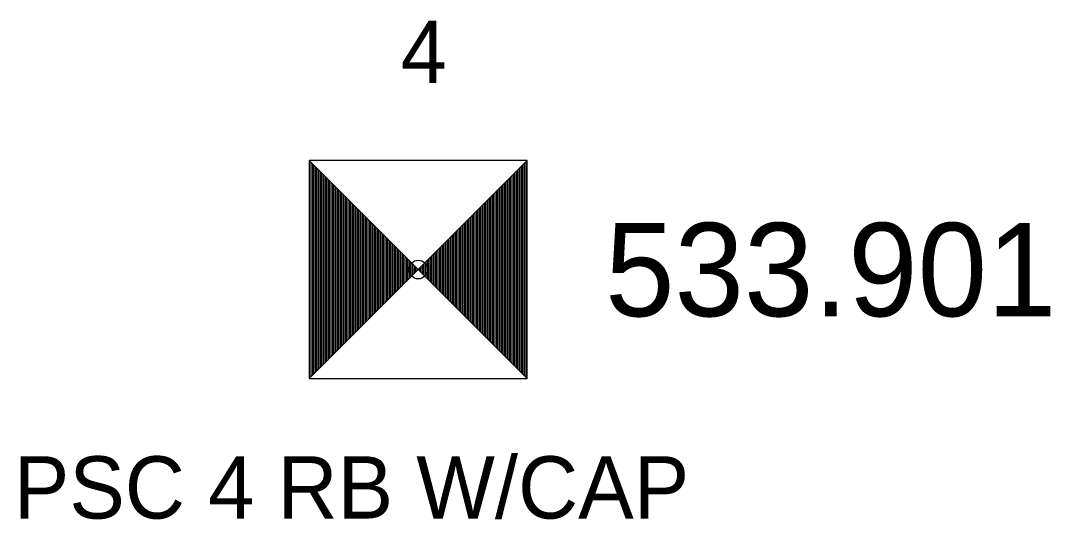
# Model space of a CAD drawing. Extents: x 1649047 to 1650429, y 896228 to 898747.
# Drawn here: x 1649763.56 to 1649780.1, y 898738.7 to 898746.72 of the extents above; entities that cross this region are included whole.
import ezdxf

# ---------------------------------------------------------------- set-up
doc = ezdxf.new("R2010")
doc.units = 0
for name, color, linetype in [('RD_HC_Survey', 7, 'Continuous'), ('RD_HC_Survey_ELEV', 7, 'Continuous'), ('RD_HC_txCode', 7, 'Continuous'), ('RD_SMD_Locator', 7, 'Continuous')]:
    doc.layers.add(name, color=color, linetype=linetype)

msp = doc.modelspace()

# ---------------------------------------------------------------- linework, layer by layer
at = {"layer": 'RD_HC_Survey'}
for p, q in [((1649768.199, 898744.466), (1649771.698, 898740.966)), ((1649771.698, 898744.466), (1649768.199, 898740.966)), ((1649768.223, 898744.441), (1649768.223, 898740.991)), ((1649768.248, 898744.417), (1649768.248, 898741.016)), ((1649768.273, 898744.392), (1649768.273, 898741.04)), ((1649768.298, 898744.367), (1649768.298, 898741.065)), ((1649768.322, 898744.342), (1649768.322, 898741.09)), ((1649771.575, 898744.342), (1649771.575, 898741.09)), ((1649771.599, 898744.367), (1649771.599, 898741.065)), ((1649771.624, 898744.392), (1649771.624, 898741.04)), ((1649771.649, 898744.417), (1649771.649, 898741.016)), ((1649771.674, 898744.441), (1649771.674, 898740.991)), ((1649768.347, 898744.318), (1649768.347, 898741.115)), ((1649768.372, 898744.293), (1649768.372, 898741.139)), ((1649768.396, 898744.268), (1649768.396, 898741.164)), ((1649768.421, 898744.243), (1649768.421, 898741.189)), ((1649768.446, 898744.219), (1649768.446, 898741.214)), ((1649768.471, 898744.194), (1649768.471, 898741.238)), ((1649768.495, 898744.169), (1649768.495, 898741.263)), ((1649771.402, 898744.169), (1649771.402, 898741.263)), ((1649771.426, 898744.194), (1649771.426, 898741.238)), ((1649771.451, 898744.219), (1649771.451, 898741.214)), ((1649771.476, 898744.243), (1649771.476, 898741.189)), ((1649771.501, 898744.268), (1649771.501, 898741.164)), ((1649771.525, 898744.293), (1649771.525, 898741.139)), ((1649771.55, 898744.318), (1649771.55, 898741.115)), ((1649768.52, 898744.144), (1649768.52, 898741.288)), ((1649768.545, 898744.12), (1649768.545, 898741.313)), ((1649768.57, 898744.095), (1649768.57, 898741.337)), ((1649768.594, 898744.07), (1649768.594, 898741.362)), ((1649768.619, 898744.045), (1649768.619, 898741.387)), ((1649768.644, 898744.021), (1649768.644, 898741.412)), ((1649768.669, 898743.996), (1649768.669, 898741.436)), ((1649771.228, 898743.996), (1649771.228, 898741.436)), ((1649771.253, 898744.021), (1649771.253, 898741.412)), ((1649771.278, 898744.045), (1649771.278, 898741.387)), ((1649771.303, 898744.07), (1649771.303, 898741.362)), ((1649771.327, 898744.095), (1649771.327, 898741.337)), ((1649771.352, 898744.12), (1649771.352, 898741.313)), ((1649771.377, 898744.144), (1649771.377, 898741.288)), ((1649768.693, 898743.971), (1649768.693, 898741.461)), ((1649768.718, 898743.946), (1649768.718, 898741.486)), ((1649768.743, 898743.922), (1649768.743, 898741.511)), ((1649768.768, 898743.897), (1649768.768, 898741.535)), ((1649768.792, 898743.872), (1649768.792, 898741.56)), ((1649768.817, 898743.847), (1649768.817, 898741.585)), ((1649771.08, 898743.847), (1649771.08, 898741.585)), ((1649771.105, 898743.872), (1649771.105, 898741.56)), ((1649771.129, 898743.897), (1649771.129, 898741.535)), ((1649771.154, 898743.922), (1649771.154, 898741.511)), ((1649771.179, 898743.946), (1649771.179, 898741.486)), ((1649771.204, 898743.971), (1649771.204, 898741.461)), ((1649768.842, 898743.823), (1649768.842, 898741.61)), ((1649768.867, 898743.798), (1649768.867, 898741.634)), ((1649768.891, 898743.773), (1649768.891, 898741.659)), ((1649768.916, 898743.748), (1649768.916, 898741.684)), ((1649768.941, 898743.724), (1649768.941, 898741.709)), ((1649768.966, 898743.699), (1649768.966, 898741.733)), ((1649768.99, 898743.674), (1649768.99, 898741.758)), ((1649770.907, 898743.674), (1649770.907, 898741.758)), ((1649770.931, 898743.699), (1649770.931, 898741.733)), ((1649770.956, 898743.724), (1649770.956, 898741.709)), ((1649770.981, 898743.748), (1649770.981, 898741.684)), ((1649771.006, 898743.773), (1649771.006, 898741.659)), ((1649771.03, 898743.798), (1649771.03, 898741.634)), ((1649771.055, 898743.823), (1649771.055, 898741.61)), ((1649769.015, 898743.649), (1649769.015, 898741.783)), ((1649769.04, 898743.625), (1649769.04, 898741.808)), ((1649769.065, 898743.6), (1649769.065, 898741.832)), ((1649769.089, 898743.575), (1649769.089, 898741.857)), ((1649769.114, 898743.55), (1649769.114, 898741.882)), ((1649769.139, 898743.526), (1649769.139, 898741.907)), ((1649769.164, 898743.501), (1649769.164, 898741.931)), ((1649770.733, 898743.501), (1649770.733, 898741.931)), ((1649770.758, 898743.526), (1649770.758, 898741.907)), ((1649770.783, 898743.55), (1649770.783, 898741.882)), ((1649770.808, 898743.575), (1649770.808, 898741.857)), ((1649770.832, 898743.6), (1649770.832, 898741.832)), ((1649770.857, 898743.625), (1649770.857, 898741.808)), ((1649770.882, 898743.649), (1649770.882, 898741.783)), ((1649769.188, 898743.476), (1649769.188, 898741.956)), ((1649769.213, 898743.451), (1649769.213, 898741.981)), ((1649769.238, 898743.427), (1649769.238, 898742.006)), ((1649769.263, 898743.402), (1649769.263, 898742.03)), ((1649769.287, 898743.377), (1649769.287, 898742.055)), ((1649769.312, 898743.353), (1649769.312, 898742.08)), ((1649770.585, 898743.353), (1649770.585, 898742.08)), ((1649770.61, 898743.377), (1649770.61, 898742.055)), ((1649770.634, 898743.402), (1649770.634, 898742.03)), ((1649770.659, 898743.427), (1649770.659, 898742.006)), ((1649770.684, 898743.451), (1649770.684, 898741.981)), ((1649770.709, 898743.476), (1649770.709, 898741.956)), ((1649769.337, 898743.328), (1649769.337, 898742.105)), ((1649769.362, 898743.303), (1649769.362, 898742.129)), ((1649769.386, 898743.278), (1649769.386, 898742.154)), ((1649769.411, 898743.254), (1649769.411, 898742.179)), ((1649769.436, 898743.229), (1649769.436, 898742.204)), ((1649769.461, 898743.204), (1649769.461, 898742.228)), ((1649769.485, 898743.179), (1649769.485, 898742.253)), ((1649770.412, 898743.179), (1649770.412, 898742.253)), ((1649770.436, 898743.204), (1649770.436, 898742.228)), ((1649770.461, 898743.229), (1649770.461, 898742.204)), ((1649770.486, 898743.254), (1649770.486, 898742.179)), ((1649770.511, 898743.278), (1649770.511, 898742.154)), ((1649770.535, 898743.303), (1649770.535, 898742.129)), ((1649770.56, 898743.328), (1649770.56, 898742.105)), ((1649769.51, 898743.155), (1649769.51, 898742.278)), ((1649769.535, 898743.13), (1649769.535, 898742.303)), ((1649769.56, 898743.105), (1649769.56, 898742.327)), ((1649769.584, 898743.08), (1649769.584, 898742.352)), ((1649769.609, 898743.056), (1649769.609, 898742.377)), ((1649769.634, 898743.031), (1649769.634, 898742.402)), ((1649769.659, 898743.006), (1649769.659, 898742.426)), ((1649770.238, 898743.006), (1649770.238, 898742.426)), ((1649770.263, 898743.031), (1649770.263, 898742.402)), ((1649770.288, 898743.056), (1649770.288, 898742.377)), ((1649770.313, 898743.08), (1649770.313, 898742.352)), ((1649770.337, 898743.105), (1649770.337, 898742.327)), ((1649770.362, 898743.13), (1649770.362, 898742.303)), ((1649770.387, 898743.155), (1649770.387, 898742.278)), ((1649769.683, 898742.981), (1649769.683, 898742.451)), ((1649769.708, 898742.957), (1649769.708, 898742.476)), ((1649769.733, 898742.932), (1649769.733, 898742.501)), ((1649769.758, 898742.907), (1649769.758, 898742.525)), ((1649769.782, 898742.882), (1649769.782, 898742.55)), ((1649769.807, 898742.858), (1649769.807, 898742.575)), ((1649769.832, 898742.833), (1649769.832, 898742.6)), ((1649770.065, 898742.833), (1649770.065, 898742.6)), ((1649770.09, 898742.858), (1649770.09, 898742.575)), ((1649770.115, 898742.882), (1649770.115, 898742.55)), ((1649770.139, 898742.907), (1649770.139, 898742.525)), ((1649770.164, 898742.932), (1649770.164, 898742.501)), ((1649770.189, 898742.957), (1649770.189, 898742.476)), ((1649770.214, 898742.981), (1649770.214, 898742.451)), ((1649769.857, 898742.808), (1649769.857, 898742.624)), ((1649769.881, 898742.783), (1649769.881, 898742.649)), ((1649769.906, 898742.759), (1649769.906, 898742.674)), ((1649769.931, 898742.734), (1649769.931, 898742.699)), ((1649769.966, 898742.734), (1649769.966, 898742.699)), ((1649769.991, 898742.759), (1649769.991, 898742.674)), ((1649770.016, 898742.783), (1649770.016, 898742.649)), ((1649770.04, 898742.808), (1649770.04, 898742.624))]:
    msp.add_line(p, q, dxfattribs=at)
msp.add_lwpolyline([(1649771.698, 898744.466), (1649768.199, 898744.466), (1649768.199, 898740.966), (1649771.698, 898740.966)], close=True, dxfattribs=at)
at = {"layer": 'RD_SMD_Locator'}
msp.add_circle((1649769.949, 898742.716), 0.15, dxfattribs=at)

# ---------------------------------------------------------------- texts
at = {"layer": 'RD_HC_Survey_ELEV'}
msp.add_text('533.901', height=1.5, dxfattribs=at).set_placement((1649772.949, 898741.966))
at = {"layer": 'RD_HC_txCode'}
for s, p in [('4', (1649769.665, 898745.716)), ('PSC 4 RB W/CAP', (1649763.452, 898738.716))]:
    msp.add_text(s, height=1, dxfattribs=at).set_placement(p)

doc.saveas('drawing.dxf')
